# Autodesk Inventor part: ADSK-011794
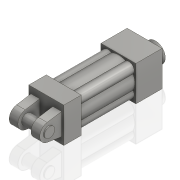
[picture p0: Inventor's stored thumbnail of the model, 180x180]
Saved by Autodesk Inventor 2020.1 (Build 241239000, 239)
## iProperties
Created: 1999-11
Part Number: ADSK-011794
Material: Aluminum
Document SubType Name: Modeling
Designer: kcovelli
Density: 2.71 g/cm^3
Appearance: Steel
Mass: 458.941 g
Surface Area: 631.515 cm^2
Volume: 169.351 cm^3
Control State: 0
Master: False
Checked Out: False
Shininess: 0.0
Length Units: 11272
Angle Units: 11279
Time Units: 11290
Mass Units: 11286
Length Display Precision: 3
Angle Display Precision: 2
Compacted: True
Dimensions: 2x2x7,5 in
Mass: 1,012 lb
DocNumber: ADSK-011794.ipt
Folder: 01 - Themengebiete\Simplification\01 - Packaging machine\
VDS_Category: 3D Komponenten
Density: 0.0
Volumn: 0.0
Area: 0.0
PropertySet Name: Model Information
Author: kcovelli
Revision Number: -
Title: Zylinder
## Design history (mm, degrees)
node "Extrusion1" dims "d0" = 38.1, "d1" = 0
node "Extrusion3" dims "d24" = 79.375, "d25" = 0
node "Shell1" dims "d26" = 3.175
node "Extrusion4" dims "d27" = 12.7, "d28" = 0
node "Extrusion5" dims "d29" = 12.7, "d30" = 0
node "Extrusion6" dims "d37" = 50.8, "d38" = 0
workplane "Work Plane1"
node "Extrusion7" dims "d43" = 47.625, "d44" = 0
node "Extrusion8" dims "d46" = 15.875, "d47" = 0
node "Extrusion9" dims "d52" = 15.875, "d53" = 0
node "Extrusion10" dims "d55" = 76.2, "d56" = 0
workplane "Work Plane4"
node "Mirror3"
workplane "Arbeitsebene5"
node "Solide1"
node "Corps solides"
node "Corps surfaciques"
sketch "Sketch1"
  geometry: L1 (-252.48, -244.003)-(-201.68, -244.003); L2 (-201.68, -244.003)-(-201.68, -294.803); L3 (-201.68, -294.803)-(-252.48, -294.803); L4 (-252.48, -294.803)-(-252.48, -244.003)
  constraints: 8 end point, 2 parallel, 1 horizontal, 1 perpendicular
  dimensions: "d3" = 50.8 distance of L1.end L2.end (= d64); "d64" = 50.8 distance between parallel lines of L2 L4
sketch "Sketch5"
  geometry: L1 (-252.48, -294.803)-(-252.48, -244.003) reference; L2 (-201.68, -294.803)-(-252.48, -294.803) reference; L3 (-252.48, -244.003)-(-201.68, -244.003) reference; L4 (-201.68, -244.003)-(-201.68, -294.803) reference; C1 r 7.938 at (-242.161, -254.322); C2 r 7.938 at (-211.999, -254.322); C3 r 7.938 at (-242.161, -284.485); C4 r 7.938 at (-211.999, -284.485); C5 r 23.812 at (-227.08, -269.403)
  constraints: 5 centre point
  dimensions: "d9" = 10.31875 distance from line of C3.centre L1; "d13" = 10.31875 distance from line of C4.centre L2 (= d9); "d14" = 10.31875 distance from line of C3.centre L2 (= d9); "d17" = 15.875 diameter of C1 (= d18); "d18" = 15.875 diameter of C3; "d19" = 15.875 diameter of C2 (= d18); "d20" = 15.875 diameter of C4 (= d18); "d21" = 25.4 distance from line of C5.centre L1; "d22" = 25.4 distance from line of C5.centre L2 (= d21); "d23" = 47.625 diameter of C5; "d57" = 15.08125 horizontal distance of C4.centre C5.centre (= d21 - d9); "d58" = 15.08125 horizontal distance of C1.centre C5.centre (= d57); "d59" = 15.08125 horizontal distance of C1.centre C5.centre; "d60" = 15.08125 horizontal distance of C2.centre C5.centre (= d59); "d61" = 15.08125 horizontal distance of C2.centre C5.centre (= d58)
sketch "Sketch6"
  geometry: L1 (-252.48, -294.803)-(-252.48, -244.003) reference; L2 (-252.48, -244.003)-(-201.68, -244.003) reference; L3 (-201.68, -244.003)-(-201.68, -294.803) reference; L4 (-201.68, -294.803)-(-252.48, -294.803) reference
sketch "Sketch7"
  geometry: L1 (-252.48, -294.803)-(-252.48, -244.003) reference; L2 (-201.68, -294.803)-(-252.48, -294.803) reference; L3 (-201.68, -244.003)-(-201.68, -294.803) reference; L4 (-252.48, -244.003)-(-201.68, -244.003) reference
sketch "Sketch8"
  geometry: L1 (-252.48, -294.803)-(-252.48, -244.003) reference; L2 (-201.68, -294.803)-(-252.48, -294.803) reference; L3 (-249.305, -253.528)-(-236.605, -253.528); L4 (-236.605, -253.528)-(-236.605, -285.278); L5 (-236.605, -285.278)-(-249.305, -285.278); L6 (-249.305, -285.278)-(-249.305, -253.528)
  constraints: 8 end point, 2 parallel, 1 horizontal, 1 perpendicular
  dimensions: "d31" = 3.175 distance between parallel lines of L6 L1; "d33" = 9.525 distance between parallel lines of L5 L2; "d36" = 12.7 distance of L4.end L5.end; "d65" = 31.75 distance between parallel lines of L3 L5
sketch "Sketch10"
  geometry: L1 (-50.8, 0)-(-50.8, 31.75) reference; L2 (-50.8, 31.75)-(0, 31.75) reference; L3 (-50.8, 0)-(0, 0) reference; C1 r 7.46 at (-31.75, 15.875)
  constraints: 1 centre point
  dimensions: "d41" = 19.05 distance from line of C1.centre L1; "d66" = 15.875 distance from line of C1.centre L3
sketch "Sketch11"
  geometry: L1 (0, 0)-(0, 31.75) reference; L2 (-50.8, 31.75)-(0, 31.75) reference; L3 (-50.8, 0)-(0, 0) reference; L4 (-29.764, 3.331)-(-50.8, 0); L5 (-29.764, 28.419)-(-50.8, 31.75); C1 r 7.46 at (-31.75, 15.875) reference; A1 r 12.7 centre (-31.75, 15.875) between (-29.764, 3.331) and (-29.764, 28.419)
  constraints: 4 end point, 2 point on circle, 2 tangent, 1 centre point, 1 coincident
  dimensions: "d45" = 12.7 radius of A1
sketch "Sketch13"
  geometry: L1 (252.48, -294.803)-(201.68, -294.803) reference; L2 (252.48, -244.003)-(252.48, -294.803) reference; C1 r 14.275 at (227.08, -269.403)
  constraints: 1 centre point
  dimensions: "d51" = 28.5496 diameter of C1; "d62" = 25.4 distance from line of C1.centre L1; "d63" = 25.4 distance from line of C1.centre L2 (= d62)
sketch "Sketch14"
  geometry: C1 r 14.275 at (0, 0) reference; C2 r 8.001 at (0, 0)
  constraints: 1 centre point, 1 coincident
  dimensions: "d54" = 16.002 diameter of C2
other parameters: "d39" = 1.5875, "d67" = -25.4
